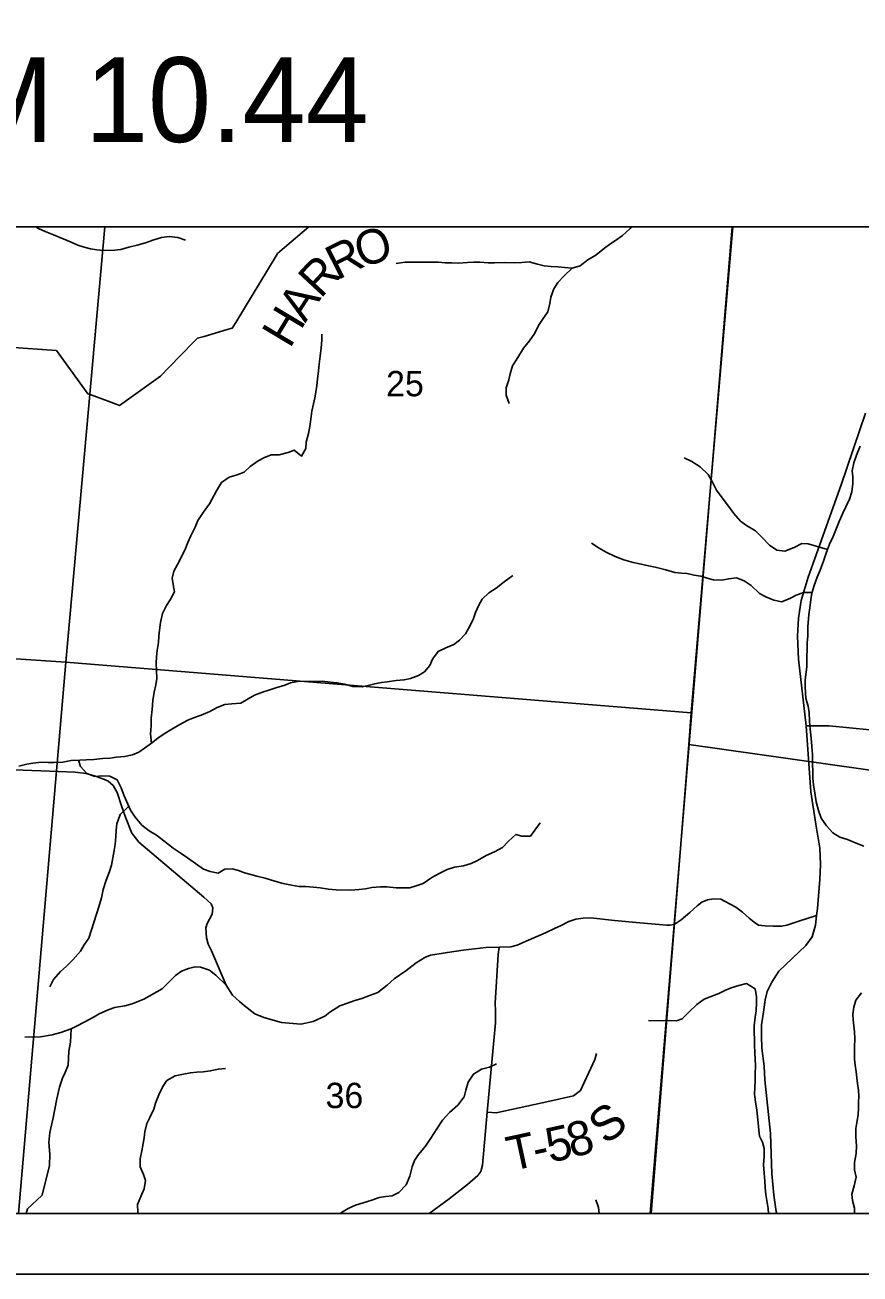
# Model space of a CAD drawing. Extents: x 0 to 34, y 0 to 22.
# Drawn here: x 24.795 to 26.174, y 14 to 16.062 of the extents above; entities that cross this region are included whole.
import ezdxf

# ---------------------------------------------------------------- set-up
doc = ezdxf.new("R2010")
doc.units = 0
for name, color, linetype in [('GM_X_Corporation', 7, 'Continuous'), ('GM_X_County_Road', 7, 'Continuous'), ('GM_X_Minor_River', 7, 'Continuous'), ('GM_X_Section_Text', 7, 'Continuous'), ('GM_X_State_Route', 7, 'Continuous'), ('GM_X_Township_Road', 7, 'Continuous'), ('GM_X_Township_Road_Text', 7, 'Continuous'), ('SH_Data', 7, 'Continuous'), ('SH_Text', 7, 'Continuous')]:
    doc.layers.add(name, color=color, linetype=linetype)

msp = doc.modelspace()

# ---------------------------------------------------------------- linework, layer by layer
at = {"layer": 'GM_X_Corporation'}
for points in [[(26.1825, 18.4635), (26.1926, 18.5708), (26.207, 18.8068), (26.2271, 19.0168), (26.2277, 19.0233), (26.2281, 19.0286), (26.3029, 19.931), (25.7174, 19.9778), (25.482, 19.99), (25.2916, 20.0037), (25.117, 20.0172), (24.3889, 20.0736), (24.2296, 20.084), (23.8215, 20.1257), (23.5167, 20.1476), (23.5167, 14.1), (25.8273, 14.1), (25.8671, 14.5774), (25.9626, 15.7291)], [(24.9264, 15.7291), (24.8621, 15.0105), (23.8295, 15.0789), (23.9154, 16.1379), (24.3169, 16.1005)], [(26.1924, 15.8415), (27.112, 15.7689), (27.0394, 14.7121), (25.8914, 14.8743), (25.8953, 14.9265), (25.9642, 15.7291)], [(25.9642, 15.7291), (25.8953, 14.9265), (24.8621, 15.0105), (24.9264, 15.7291)], [(25.9626, 15.7291), (25.8671, 14.5774), (25.8273, 14.1), (30.3167, 14.1)]]:
    msp.add_lwpolyline(points, dxfattribs=at)
for points in [[(23.7459, 14.1), (24.7842, 14.1), (24.8621, 15.0105), (23.8295, 15.0789)], [(24.7842, 14.1), (25.8293, 14.1), (25.8914, 14.8743), (25.8953, 14.9265), (24.8621, 15.0105)], [(25.8293, 14.1), (26.9884, 14.1), (27.0394, 14.7121), (25.8914, 14.8743)]]:
    msp.add_lwpolyline(points, close=True, dxfattribs=at)
at = {"layer": 'GM_X_County_Road'}
for points in [[(24.7773, 14.8327), (24.8494, 14.8299), (24.8778, 14.8285), (24.8959, 14.8263), (24.9129, 14.8217), (24.9318, 14.8143), (24.9406, 14.8064), (24.947, 14.7951), (24.9541, 14.7731), (24.9605, 14.7542), (24.9713, 14.7282), (24.983, 14.7129), (25.0904, 14.622), (25.1024, 14.6115), (25.1052, 14.6048), (25.1037, 14.5943), (25.0954, 14.5786), (25.0932, 14.5718), (25.0947, 14.5549), (25.0974, 14.5445), (25.1028, 14.5336), (25.1268, 14.477)], [(25.8601, 14.5762), (25.8673, 14.5769), (25.8786, 14.5851), (25.8928, 14.5971), (25.9051, 14.6079), (25.9128, 14.6139), (25.922, 14.6181), (25.9318, 14.6193), (25.9442, 14.6187), (25.9511, 14.6152), (25.969, 14.6057), (25.98, 14.5974), (25.9907, 14.5875), (25.999, 14.581), (26.0065, 14.5759), (26.0175, 14.5749), (26.0305, 14.5741), (26.0445, 14.5743), (26.0534, 14.5763), (26.0732, 14.5826), (26.1019, 14.5918)], [(25.1268, 14.477), (25.1377, 14.4607), (25.149, 14.4499), (25.1567, 14.4436), (25.1745, 14.4297), (25.1891, 14.4238), (25.2182, 14.4155), (25.2503, 14.4123), (25.2706, 14.4169), (25.2901, 14.4259), (25.2985, 14.4326), (25.3146, 14.4428), (25.3277, 14.4472), (25.3377, 14.4509), (25.3513, 14.4551), (25.3654, 14.4602), (25.3776, 14.4649), (25.3931, 14.4767), (25.4048, 14.4875), (25.424, 14.5006), (25.4409, 14.5137), (25.4554, 14.5226), (25.4648, 14.5264), (25.4925, 14.5311), (25.5187, 14.5348), (25.5558, 14.5391), (25.5782, 14.5397), (25.5975, 14.5404), (25.6078, 14.543), (25.6225, 14.5497), (25.6393, 14.557), (25.6546, 14.5636), (25.6706, 14.5709), (25.6794, 14.5752), (25.6933, 14.5819), (25.7047, 14.5859), (25.7169, 14.5878), (25.7296, 14.5882), (25.7683, 14.5835), (25.8103, 14.5797), (25.8549, 14.5758), (25.8601, 14.5762)], [(24.7945, 14.3913), (24.8204, 14.3919), (24.8398, 14.3951), (24.8541, 14.3986), (24.8712, 14.4048), (24.8798, 14.4092), (24.8936, 14.4165), (24.9089, 14.4245), (24.917, 14.4295), (24.9283, 14.4345), (24.9427, 14.4399), (24.9595, 14.4431), (24.9717, 14.4463), (24.9911, 14.454), (25.0214, 14.4707), (25.0332, 14.4829), (25.0431, 14.4929), (25.0535, 14.5001), (25.0649, 14.5046), (25.0757, 14.5074), (25.0848, 14.5069), (25.0997, 14.5015), (25.1101, 14.4933), (25.1268, 14.477)]]:
    msp.add_lwpolyline(points, dxfattribs=at)
at = {"layer": 'GM_X_Minor_River'}
for points in [[(24.8127, 15.7291), (24.8168, 15.7264), (24.8281, 15.7214), (24.8417, 15.7157), (24.858, 15.7092), (24.8712, 15.7038), (24.8822, 15.6988), (24.8927, 15.6954), (24.9029, 15.6927), (24.9135, 15.6911), (24.9256, 15.69), (24.943, 15.6907), (24.9529, 15.6918), (24.9661, 15.6955), (24.9798, 15.6989), (24.9938, 15.7026), (25.0074, 15.7075), (25.0203, 15.7116), (25.0328, 15.7131), (25.0471, 15.7115), (25.0596, 15.7073)], [(25.7966, 15.7291), (25.7943, 15.7266), (25.7814, 15.7145), (25.7719, 15.7077), (25.7625, 15.7017), (25.7518, 15.6941), (25.7378, 15.6824), (25.7245, 15.6745), (25.712, 15.6647), (25.6988, 15.6606), (25.6859, 15.6621), (25.6757, 15.6633), (25.664, 15.6637), (25.6522, 15.6649), (25.6413, 15.6672), (25.6273, 15.6711), (25.6156, 15.67), (25.6038, 15.6696), (25.5876, 15.6701), (25.5702, 15.6698), (25.56, 15.6698), (25.546, 15.671), (25.5357, 15.671), (25.5255, 15.6703), (25.5108, 15.6692), (25.4998, 15.6697), (25.4888, 15.6697), (25.4779, 15.6705), (25.4635, 15.6709), (25.4472, 15.6706), (25.437, 15.6706), (25.4226, 15.6707), (25.4079, 15.6685)], [(25.6988, 15.6606), (25.6851, 15.6481), (25.6748, 15.6372), (25.6684, 15.627), (25.6634, 15.6129), (25.6618, 15.6027), (25.6584, 15.5887), (25.6496, 15.5762), (25.6432, 15.566), (25.6367, 15.5535), (25.6283, 15.5411), (25.6184, 15.5286), (25.6086, 15.5135), (25.6002, 15.4995), (25.596, 15.4862), (25.5937, 15.4764), (25.5898, 15.4631), (25.5898, 15.451), (25.5946, 15.4373)], [(25.0035, 14.8762), (25.0021, 14.8918), (25.0029, 14.9051), (25.0033, 14.9176), (25.0049, 14.932), (25.0061, 14.9471), (25.008, 14.9608), (25.0111, 14.9729), (25.0127, 14.9835), (25.012, 14.9964), (25.0116, 15.0089), (25.012, 15.0191), (25.0132, 15.0294), (25.0152, 15.0426), (25.016, 15.0532), (25.0171, 15.0631), (25.0187, 15.076), (25.0221, 15.0904), (25.0282, 15.1036), (25.0343, 15.1134), (25.0416, 15.1263), (25.0397, 15.1388), (25.0379, 15.149), (25.0406, 15.1608), (25.0467, 15.1718), (25.0585, 15.1952), (25.0638, 15.2077), (25.0684, 15.2187), (25.0756, 15.2334), (25.0802, 15.244), (25.089, 15.2576), (25.0996, 15.272), (25.111, 15.2932), (25.1194, 15.3068), (25.1319, 15.3158), (25.1452, 15.3196), (25.1569, 15.3241), (25.1668, 15.3335), (25.1797, 15.343), (25.1895, 15.3475), (25.2013, 15.3524), (25.2145, 15.3527), (25.2293, 15.3564), (25.2391, 15.3606), (25.2516, 15.3507), (25.2585, 15.3631), (25.2592, 15.3737), (25.2631, 15.3878), (25.2654, 15.3995), (25.267, 15.4116), (25.2685, 15.4249), (25.2712, 15.4366), (25.2735, 15.4465), (25.2754, 15.4563), (25.277, 15.4673), (25.2778, 15.4775), (25.2797, 15.4912), (25.2809, 15.5022), (25.2825, 15.5158), (25.284, 15.5291), (25.2852, 15.5419), (25.2853, 15.5518)], [(26.1743, 15.3669), (26.1682, 15.3522), (26.164, 15.3397), (26.1613, 15.326), (26.162, 15.3162), (26.162, 15.3052), (26.1604, 15.2915), (26.1566, 15.2794), (26.1505, 15.2669), (26.1455, 15.2563), (26.1394, 15.2423), (26.1295, 15.2177), (26.1238, 15.2049), (26.1181, 15.1905), (26.1138, 15.1769), (26.1081, 15.1621), (26.1032, 15.1504), (26.0982, 15.1371), (26.0944, 15.1243), (26.0928, 15.114), (26.0909, 15.1), (26.0897, 15.089), (26.0881, 15.0686), (26.0877, 15.0538), (26.0869, 15.042), (26.0865, 15.0326), (26.0864, 15.0178), (26.086, 15.003), (26.0836, 14.9803), (26.0836, 14.97), (26.0839, 14.9598), (26.0846, 14.9503), (26.0884, 14.9378), (26.0902, 14.9272), (26.0905, 14.9128), (26.0916, 14.8999), (26.0931, 14.8847), (26.0942, 14.8711), (26.0953, 14.8578), (26.0956, 14.843), (26.0959, 14.829), (26.0959, 14.8195), (26.0973, 14.8074), (26.0996, 14.7945), (26.1018, 14.7797), (26.1055, 14.7656), (26.11, 14.7527), (26.1187, 14.7398), (26.1292, 14.7284), (26.1409, 14.7212), (26.1534, 14.7173), (26.1677, 14.7112), (26.1806, 14.7066)], [(26.1203, 15.1962), (26.1018, 15.2016), (26.0882, 15.2058), (26.078, 15.2062), (26.0651, 15.1998), (26.05, 15.1934), (26.0364, 15.1954), (26.0247, 15.2034), (26.0126, 15.2163), (26.0013, 15.2273), (25.9866, 15.2357), (25.9764, 15.2433), (25.9658, 15.2559), (25.9568, 15.2677), (25.9463, 15.2814), (25.9372, 15.2943), (25.9305, 15.3076), (25.9233, 15.3201), (25.9098, 15.3327), (25.8962, 15.3418), (25.8837, 15.3479)], [(26.0947, 15.1254), (26.0807, 15.1254), (26.0686, 15.1209), (26.0591, 15.116), (26.0451, 15.11), (26.0319, 15.1127), (26.0187, 15.1181), (26.0081, 15.1238), (25.9945, 15.1368), (25.9825, 15.1448), (25.97, 15.1494), (25.9571, 15.1479), (25.9458, 15.1457), (25.9318, 15.1465), (25.9216, 15.1492), (25.911, 15.1522), (25.9, 15.1538), (25.8887, 15.1565), (25.8789, 15.1573), (25.8679, 15.1585), (25.8531, 15.1627), (25.8358, 15.1669), (25.8248, 15.1692), (25.8127, 15.1723), (25.7991, 15.175), (25.784, 15.1792), (25.7696, 15.1846), (25.7549, 15.1919), (25.7432, 15.1987), (25.7307, 15.2067)], [(25.1976, 14.9639), (25.2093, 14.968), (25.2237, 14.9725), (25.2332, 14.9762), (25.2479, 14.9788), (25.2601, 14.9784), (25.2725, 14.9784), (25.2854, 14.9791), (25.2994, 14.9775), (25.31, 14.9763), (25.3228, 14.974), (25.3361, 14.9702), (25.3519, 14.9694), (25.3618, 14.9716), (25.3724, 14.9746), (25.3834, 14.9768), (25.3932, 14.9779), (25.408, 14.9798), (25.4208, 14.9812), (25.4314, 14.9835), (25.4447, 14.9883), (25.4546, 14.9944), (25.4633, 15.005), (25.4679, 15.0152), (25.477, 15.028), (25.4899, 15.0337), (25.5031, 15.0397), (25.5126, 15.0465), (25.5221, 15.057), (25.5301, 15.0707), (25.5358, 15.0824), (25.5389, 15.0922), (25.5442, 15.1043), (25.55, 15.1145), (25.561, 15.1247), (25.5731, 15.1327), (25.586, 15.1428), (25.6004, 15.1534)], [(24.7844, 14.8388), (24.7976, 14.8418), (24.8075, 14.8433), (24.8222, 14.8451), (24.8332, 14.8447), (24.8431, 14.8447), (24.8571, 14.845), (24.8711, 14.848), (24.8851, 14.8487), (24.8957, 14.849), (24.9085, 14.8497), (24.9229, 14.8512), (24.935, 14.8519), (24.946, 14.8537), (24.9592, 14.8548), (24.9725, 14.8571), (24.9827, 14.8619), (24.9922, 14.8684), (25.0036, 14.8763), (25.0142, 14.8846), (25.0248, 14.8917), (25.0373, 14.8996), (25.0506, 14.9076), (25.0635, 14.9143), (25.073, 14.9181), (25.0858, 14.923), (25.1002, 14.929), (25.1124, 14.9354), (25.1249, 14.9403), (25.1366, 14.9417), (25.151, 14.9428), (25.1635, 14.95), (25.1737, 14.9556), (25.187, 14.9605), (25.1976, 14.9639)], [(24.8829, 14.8486), (24.8865, 14.8381), (24.8971, 14.8263), (24.9099, 14.8217), (24.9217, 14.8224), (24.9349, 14.822), (24.947, 14.8158), (24.9534, 14.8026), (24.9586, 14.7897), (24.9646, 14.7756), (24.9691, 14.7661), (24.9766, 14.7543), (24.9879, 14.7414), (25, 14.7319), (25.0117, 14.7246), (25.0238, 14.7155), (25.0396, 14.7029), (25.0525, 14.6945), (25.0634, 14.6873), (25.0762, 14.6778), (25.0898, 14.6686), (25.1004, 14.6648), (25.114, 14.6621), (25.125, 14.6685), (25.1367, 14.6692), (25.1473, 14.6665), (25.1571, 14.6627), (25.1677, 14.6596), (25.1775, 14.6569), (25.1915, 14.6535), (25.2074, 14.6489), (25.221, 14.645), (25.235, 14.6419), (25.2471, 14.64), (25.258, 14.6396), (25.2713, 14.6388), (25.2822, 14.6376), (25.2959, 14.6353), (25.3087, 14.6341), (25.3329, 14.634), (25.3465, 14.6347), (25.3571, 14.6362), (25.3677, 14.6384), (25.3817, 14.6395), (25.3923, 14.6391), (25.4078, 14.6379), (25.4305, 14.6378), (25.4411, 14.6408), (25.4525, 14.6449), (25.4669, 14.6547), (25.4787, 14.6611), (25.4923, 14.6679), (25.5044, 14.6716), (25.5188, 14.6742), (25.5317, 14.678), (25.5423, 14.6829), (25.5563, 14.6912), (25.5703, 14.6972), (25.5836, 14.7043), (25.5935, 14.7145), (25.6053, 14.7258), (25.6155, 14.7228), (25.6295, 14.7231), (25.6367, 14.7329), (25.6458, 14.745)], [(24.9662, 14.7723), (24.9517, 14.759), (24.9463, 14.7431), (24.9455, 14.7328), (24.9447, 14.7222), (24.9436, 14.7094), (24.942, 14.6995), (24.9397, 14.6874), (24.9378, 14.6753), (24.9343, 14.6647), (24.9286, 14.6503), (24.924, 14.6348), (24.9209, 14.6211), (24.9167, 14.6064), (24.9129, 14.5943), (24.9087, 14.5806), (24.9041, 14.5666), (24.8999, 14.5545), (24.8922, 14.5435), (24.8865, 14.533), (24.8736, 14.519), (24.863, 14.508), (24.8535, 14.4997), (24.8417, 14.4861), (24.8356, 14.474)], [(26.0228, 14.1), (26.0221, 14.1084), (26.0203, 14.1213), (26.0184, 14.1315), (26.0173, 14.1429), (26.017, 14.1531), (26.0159, 14.1664), (26.0148, 14.1801), (26.0156, 14.1941), (26.0157, 14.2073), (26.0131, 14.2176), (26.0082, 14.2275), (26.0067, 14.2377), (26.006, 14.2494), (26.0049, 14.2597), (26.0038, 14.2711), (26.0016, 14.2839), (25.9997, 14.2968), (26.0005, 14.3078), (26.001, 14.3203), (26.0006, 14.3298), (26.0014, 14.3442), (26.0011, 14.3548), (26.0004, 14.3654), (26, 14.3783), (25.9997, 14.3882), (25.9994, 14.3977), (25.999, 14.4098), (26.001, 14.4242), (26.0025, 14.4348), (26.003, 14.4484), (26.003, 14.4583), (26.0008, 14.4708), (25.9864, 14.4796), (25.9739, 14.4766), (25.9611, 14.4725), (25.9508, 14.4683), (25.9406, 14.4634), (25.9266, 14.4578), (25.9167, 14.4537), (25.9046, 14.445), (25.8917, 14.4329), (25.8803, 14.4216), (25.8708, 14.4178), (25.8591, 14.4187), (25.847, 14.4183), (25.8247, 14.4184)], [(26.1648, 14.1), (26.1651, 14.109), (26.1618, 14.1215), (26.1607, 14.1321), (26.1645, 14.1458), (26.1676, 14.1598), (26.165, 14.1723), (26.165, 14.184), (26.1677, 14.1992), (26.1685, 14.2117), (26.1674, 14.2265), (26.1671, 14.2401), (26.1694, 14.2534), (26.171, 14.2628), (26.1714, 14.2742), (26.1718, 14.2837), (26.1719, 14.2939), (26.1715, 14.3038), (26.17, 14.3144), (26.1686, 14.3242), (26.1678, 14.3341), (26.166, 14.3447), (26.1649, 14.3546), (26.165, 14.3747), (26.1654, 14.3891), (26.1647, 14.3997), (26.1636, 14.4099), (26.1629, 14.4198), (26.1621, 14.4293), (26.1641, 14.4406), (26.1672, 14.4524), (26.1767, 14.4644)], [(24.981, 14.1), (24.981, 14.1017), (24.9807, 14.1146), (24.986, 14.1282), (24.9918, 14.1407), (24.9937, 14.1543), (24.9907, 14.1646), (24.9847, 14.1771), (24.9848, 14.19), (24.9878, 14.2036), (24.9898, 14.2154), (24.9913, 14.2248), (24.9929, 14.2347), (24.9959, 14.2483), (25.0009, 14.2585), (25.0074, 14.2721), (25.0104, 14.282), (25.0158, 14.296), (25.0223, 14.3096), (25.0291, 14.3194), (25.0428, 14.327), (25.0568, 14.3299), (25.0681, 14.3322), (25.0787, 14.3333), (25.0889, 14.3336), (25.1007, 14.3355), (25.1143, 14.3384), (25.126, 14.3395)], [(25.4379, 14.1875), (25.4448, 14.1974), (25.4562, 14.211), (25.4653, 14.2242), (25.4752, 14.2397), (25.4843, 14.2541), (25.4961, 14.2669), (25.5098, 14.279), (25.5204, 14.2926), (25.5231, 14.3036), (25.5269, 14.3168), (25.5357, 14.33), (25.5486, 14.338), (25.5618, 14.3417), (25.5736, 14.347)], [(25.3155, 14.1), (25.3177, 14.1016), (25.3287, 14.108), (25.3404, 14.1136), (25.3533, 14.1177), (25.3677, 14.1222), (25.3795, 14.1264), (25.3908, 14.1282), (25.4014, 14.1293), (25.412, 14.1346), (25.4242, 14.1474), (25.4303, 14.1618), (25.4345, 14.1769), (25.4379, 14.1875)], [(25.7432, 14.1), (25.7422, 14.1098), (25.7377, 14.1224)]]:
    msp.add_lwpolyline(points, dxfattribs=at)
at = {"layer": 'GM_X_State_Route'}
msp.add_lwpolyline([(26.0368, 14.1), (26.0356, 14.1033), (26.0315, 14.1304), (26.0282, 14.1654), (26.0262, 14.2319), (26.0167, 14.3207), (26.0155, 14.343), (26.0121, 14.373), (26.0111, 14.3927), (26.0114, 14.4113), (26.0147, 14.4323), (26.0175, 14.4525), (26.0205, 14.4663), (26.0282, 14.4818), (26.0397, 14.4999), (26.0845, 14.5423), (26.0948, 14.5566), (26.1006, 14.576), (26.1019, 14.5918), (26.1036, 14.6036), (26.1074, 14.6513), (26.1086, 14.6761), (26.1074, 14.7031), (26.1012, 14.743), (26.0926, 14.796), (26.0851, 14.9052), (26.0726, 15.0153), (26.0707, 15.0532), (26.0722, 15.0827), (26.0771, 15.1123), (26.0886, 15.1506), (26.1429, 15.303), (26.1832, 15.4214)], dxfattribs=at)
at = {"layer": 'GM_X_Township_Road'}
for points in [[(24.7678, 15.5304), (24.8467, 15.525), (24.8584, 15.5092), (24.8932, 15.4611), (24.8986, 15.4536), (24.9084, 15.4499), (24.9455, 15.4361), (24.9506, 15.4342), (24.9622, 15.4425), (25.0185, 15.4828), (25.0323, 15.4969), (25.0738, 15.5393), (25.0795, 15.5451), (25.0907, 15.5483), (25.1287, 15.5594), (25.1372, 15.5618), (25.1429, 15.5711), (25.2096, 15.681), (25.2119, 15.6849), (25.2234, 15.6948), (25.2633, 15.7291)], [(26.0851, 14.9052), (26.1229, 14.9053), (26.1905, 14.8985)], [(25.5782, 14.5397), (25.5764, 14.5276), (25.5711, 14.4473), (25.5718, 14.4339), (25.5718, 14.4145), (25.5584, 14.267), (25.5505, 14.1797), (25.5475, 14.1695), (25.5429, 14.1628), (25.5256, 14.148), (25.4955, 14.1242), (25.4621, 14.1)], [(24.7969, 14.1), (24.7989, 14.1079), (24.8223, 14.1296), (24.8231, 14.1304), (24.8353, 14.1794), (24.8357, 14.1977), (24.8342, 14.2172), (24.8357, 14.2337), (24.8414, 14.2577), (24.8473, 14.2893), (24.8518, 14.3085), (24.8567, 14.3233), (24.8608, 14.3327), (24.8663, 14.3447), (24.8674, 14.3681), (24.87, 14.3829), (24.8712, 14.4048)], [(25.7388, 14.364), (25.7358, 14.354), (25.7122, 14.3028), (25.7008, 14.2943), (25.6618, 14.2856), (25.5728, 14.2663), (25.5584, 14.267)]]:
    msp.add_lwpolyline(points, dxfattribs=at)
at = {"layer": 'SH_Data'}
for points in [[(23.4167, 21), (30.4167, 21), (30.4167, 14), (23.4167, 14)], [(23.5167, 20.9), (30.3167, 20.9), (30.3167, 14.1), (23.5167, 14.1)], [(24.3169, 16.5691), (26.1924, 16.5691), (26.1924, 15.7291), (24.3169, 15.7291)]]:
    msp.add_lwpolyline(points, close=True, dxfattribs=at)

# ---------------------------------------------------------------- texts
at = {"layer": 'GM_X_Section_Text'}
for s, p in [('25', (25.3912, 15.4493)), ('36', (25.2912, 14.2739))]:
    msp.add_text(s, height=0.04186, rotation=0, dxfattribs=at).set_placement(p)
at = {"layer": 'GM_X_Township_Road_Text'}
for s, rotation, p in [('O', 18.0018, (25.35, 15.6607)), ('R', 26.9525, (25.3106, 15.6404)), ('R', 47.0565, (25.283, 15.6094)), ('A', 57.3617, (25.2577, 15.5695)), ('H', 59.0925, (25.2322, 15.5269)), ('S', 38.5258, (25.7545, 14.2119)), ('8', 14.601, (25.6979, 14.1916)), ('T', 12.2282, (25.5974, 14.1697)), ('5', 12.3856, (25.6617, 14.1836)), ('-', 12.2624, (25.6389, 14.1787))]:
    msp.add_text(s, height=0.0568, rotation=rotation, dxfattribs=at).set_placement(p)
at = {"layer": 'SH_Text'}
msp.add_text('SLM 10.44', height=0.14, dxfattribs=at).set_placement((24.4569, 15.8691))

doc.saveas('drawing.dxf')
